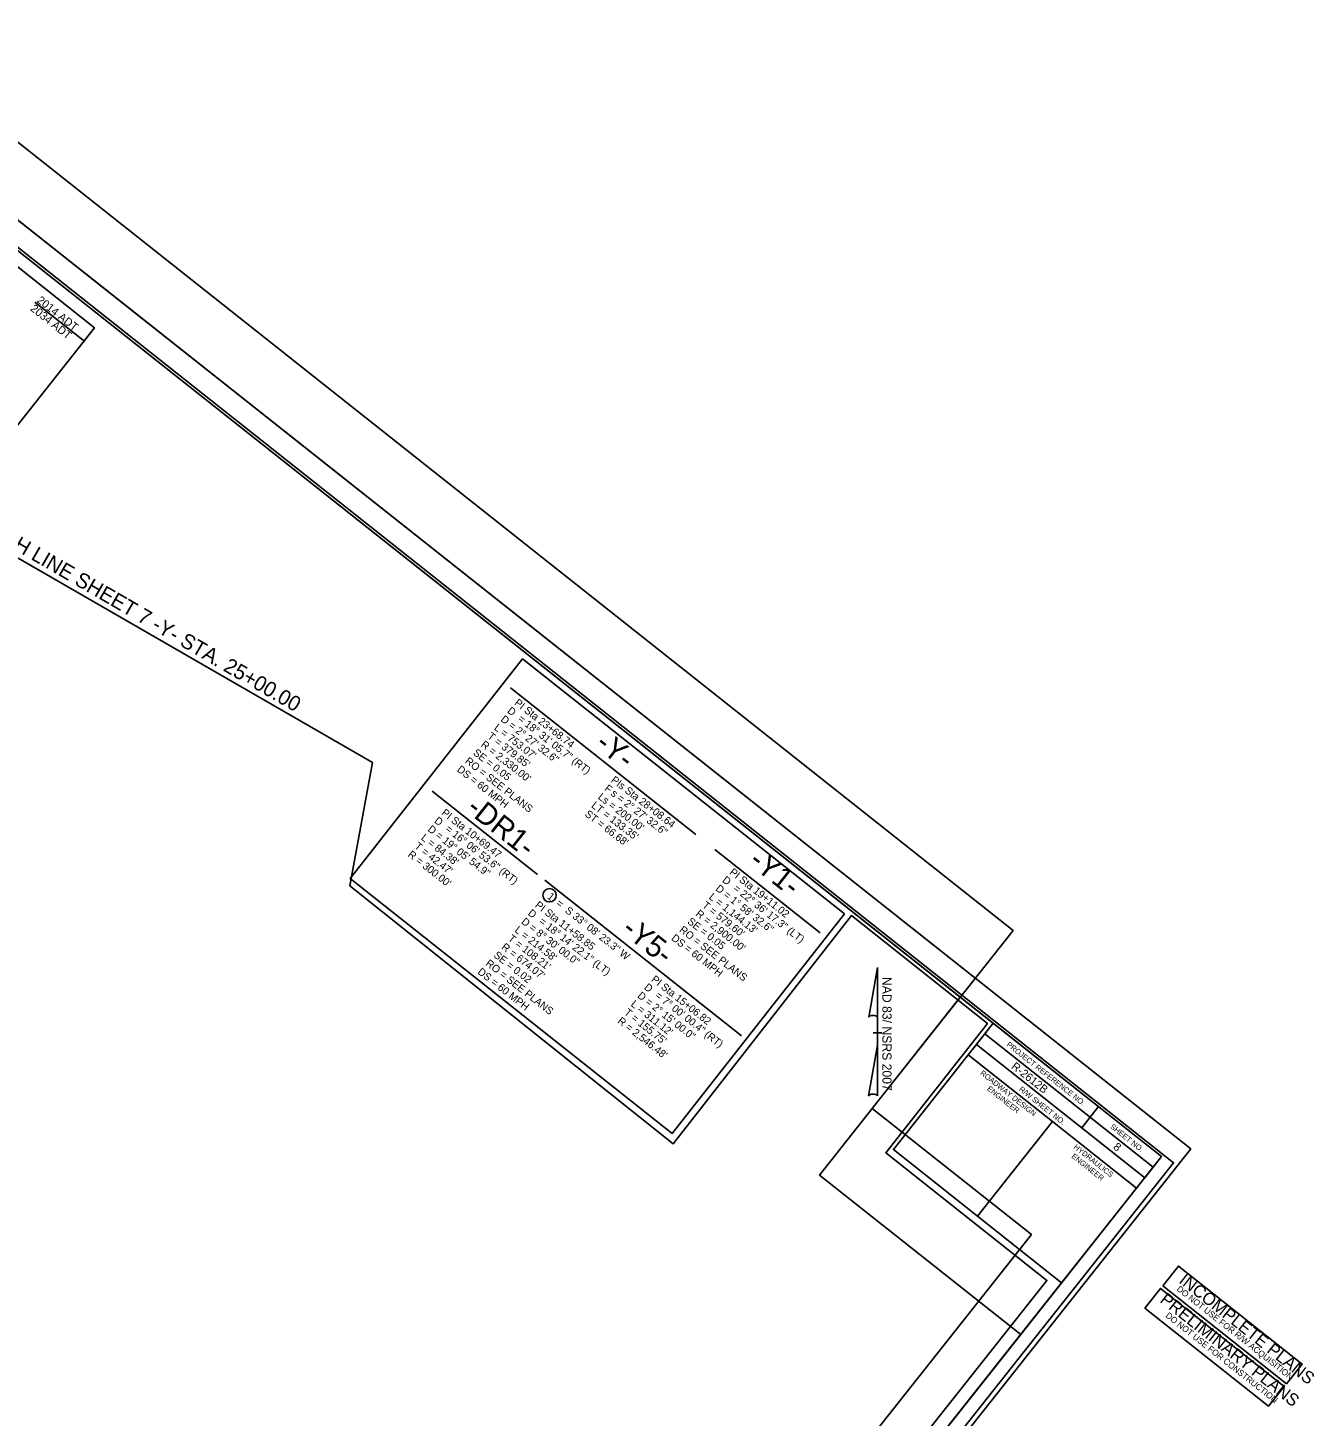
# Model space of a CAD drawing. Extents: x 1781865 to 1783979, y 813086 to 815120.
# Drawn here: x 1782780 to 1783979, y 813782 to 815076 of the extents above; entities that cross this region are included whole.
import ezdxf

# ---------------------------------------------------------------- set-up
doc = ezdxf.new("R2010")
doc.units = 0
for name, color, linetype in [('Matchline', 7, 'Continuous'), ('Matchline Text', 7, 'Continuous'), ('Old_Level_45', 7, 'Continuous'), ('Prop Horizontal Alignment Curve and Spiral Data', 7, 'Continuous'), ('Prop Horizontal Alignment Direction Label', 7, 'Continuous'), ('Prop Horizontal Alignment Station Label', 7, 'Continuous'), ('Prop North Arrow NAD83 for Plan Sheets CELL', 7, 'Continuous'), ('Sheet Clip Boundary CELL', 7, 'Continuous'), ('Sheet Cutting Line CELL', 7, 'Continuous'), ('Sheet Data Field CELL', 7, 'Continuous'), ('Sheet Layout Plan Border', 7, 'Continuous'), ('Sheet North Arrow Point CELL', 7, 'Continuous'), ('Sheet Plan CELL', 7, 'Continuous'), ('Sheet Plan Layout CELL', 7, 'Continuous'), ('Sheet Plot Border Inside CELL', 7, 'Continuous'), ('Sheet Plot Border Outside CELL', 7, 'Continuous'), ('Sheet Sticker Incomplete CELL', 7, 'Continuous'), ('Sheet Sticker Preliminary CELL', 7, 'Continuous')]:
    doc.layers.add(name, color=color, linetype=linetype)

msp = doc.modelspace()

# ---------------------------------------------------------------- linework, layer by layer
at = {"layer": 'Matchline'}
msp.add_line((1783101.5, 814390.8), (1782552.2, 814707.5), dxfattribs=at)
at = {"layer": 'Old_Level_45'}
msp.add_line((1782786.8, 814819.8), (1782833.2, 814783.1), dxfattribs=at)
msp.add_lwpolyline([(1782528.7, 814764.8), (1782664.8, 814936.7), (1782842.3, 814796.1), (1782706.3, 814624.2)], close=True, dxfattribs=at)
at = {"layer": 'Prop Horizontal Alignment Curve and Spiral Data'}
msp.add_circle((1783266.5, 814267.1), 6.26, dxfattribs=at)
at = {"layer": 'Prop Horizontal Alignment Station Label'}
for p, q in [((1783230.2, 814460.6), (1783402.9, 814323.8)), ((1783157.2, 814364.2), (1783255.3, 814286.6)), ((1783420.6, 814309.8), (1783518.7, 814232.2)), ((1783262.1, 814281.2), (1783445.5, 814136))]:
    msp.add_line(p, q, dxfattribs=at)
msp.add_lwpolyline([(1783241.3, 814487.4), (1783541.4, 814249.8), (1783380.8, 814045), (1783080.7, 814282.6)], close=True, dxfattribs=at)
at = {"layer": 'Prop North Arrow NAD83 for Plan Sheets CELL'}
for p, q in [((1783564, 814153.6), (1783572.2, 814199.9)), ((1783572.2, 814199.9), (1783572.2, 814199.9)), ((1783572.2, 814199.9), (1783572.2, 814199.9)), ((1783572.2, 814199.9), (1783572.2, 814152.1)), ((1783572.2, 814127.3), (1783572.2, 814153.5)), ((1783572.2, 814152.1), (1783572.2, 814153.5)), ((1783571.8, 814138.9), (1783568.2, 814138.9)), ((1783568.2, 814138.9), (1783568.2, 814138.9)), ((1783568.3, 814138.9), (1783576.3, 814138.9)), ((1783572.2, 814127.3), (1783563.9, 814080.1)), ((1783572.3, 814080.3), (1783572.2, 814127.3))]:
    msp.add_line(p, q, dxfattribs=at)
for centre, start_param, end_param in [((1783568.1, 814153.1), 0.216388, 2.908219), ((1783568.1, 814079.9), 0.201328, 3.141593)]:
    msp.add_ellipse(centre, major_axis=(4.23, -0.03), ratio=0.461098, start_param=start_param, end_param=end_param, dxfattribs=at)
at = {"layer": 'Sheet Clip Boundary CELL'}
msp.add_lwpolyline([(1782552.2, 814707.5), (1782111.4, 814173.2), (1782528.7, 813842.8), (1782497.5, 813772.1), (1782783.1, 813661.2), (1782870.1, 813592.2), (1782852, 813569.4), (1783166.6, 813320.4), (1783243.8, 813293.9), (1783730.1, 813908.2), (1783580.1, 814026.9), (1783674.7, 814147.7), (1783547.9, 814248.1), (1783381.9, 814035.5), (1783080.3, 814276), (1783101.5, 814390.8)], close=True, dxfattribs=at)
at = {"layer": 'Sheet Cutting Line CELL'}
msp.add_line((1783864.3, 814030.7), (1782544.4, 815075.6), dxfattribs=at)
at = {"layer": 'Sheet Layout Plan Border'}
msp.add_lwpolyline([(1782097.5, 814162.5), (1783195.2, 813293.5), (1783715.7, 813950.9), (1783567.3, 814068.4), (1783698.6, 814234.2), (1782749.3, 814985.7)], close=True, dxfattribs=at)
at = {"layer": 'Sheet North Arrow Point CELL'}
msp.add_line((1783630.7, 814194.9), (1783630.7, 814194.9), dxfattribs=at)
at = {"layer": 'Sheet Plan CELL'}
for p, q in [((1783672.3, 814137.9), (1783829.2, 814013.7)), ((1783664.6, 814128.1), (1783656.8, 814118.3)), ((1783664.6, 814128.1), (1783821.4, 814003.9)), ((1783664.6, 814128.1), (1783821.4, 814003.9)), ((1783778.1, 814070.1), (1783762.6, 814050.5)), ((1783735.3, 814056.2), (1783665.5, 813968))]:
    msp.add_line(p, q, dxfattribs=at)
for points in [[(1783837, 814023.6), (1782660.9, 814954.7), (1782009.2, 814131.4), (1783185.2, 813200.3)], [(1782009.2, 814131.4), (1782660.9, 814954.7), (1783680.1, 814147.8), (1783587, 814030.1), (1783743.8, 813905.9), (1783185.2, 813200.3)], [(1783680.1, 814147.8), (1783837, 814023.6), (1783821.4, 814003.9), (1783664.6, 814128.1)], [(1783656.8, 814118.3), (1783735.3, 814056.2), (1783665.4, 813968), (1783587, 814030.1)], [(1783735.3, 814056.2), (1783813.7, 813994.1), (1783743.8, 813905.9), (1783665.4, 813968)]]:
    msp.add_lwpolyline(points, close=True, dxfattribs=at)
at = {"layer": 'Sheet Plan Layout CELL'}
for points in [[(1782660.9, 814954.7), (1782009.2, 814131.4), (1783185.2, 813200.4), (1783705.7, 813857.8), (1783518.1, 814006.3), (1783649.4, 814172.1)], [(1783518.1, 814006.3), (1783705.7, 813857.8), (1783837, 814023.6), (1783649.4, 814172.1)]]:
    msp.add_lwpolyline(points, close=True, dxfattribs=at)
at = {"layer": 'Sheet Plot Border Inside CELL'}
msp.add_lwpolyline([(1781887.3, 814224.7), (1783193.5, 813190.6), (1783848.3, 814017.8), (1782542.1, 815051.9)], close=True, dxfattribs=at)
at = {"layer": 'Sheet Plot Border Outside CELL'}
msp.add_lwpolyline([(1781864.7, 814217.1), (1783184.6, 813172.1), (1783864.3, 814030.7), (1782544.4, 815075.6)], close=True, dxfattribs=at)
at = {"layer": 'Sheet Sticker Incomplete CELL'}
msp.add_lwpolyline([(1783838.1, 813903), (1783852.7, 813921.5), (1783968, 813830.2), (1783953.4, 813811.8)], close=True, dxfattribs=at)
at = {"layer": 'Sheet Sticker Preliminary CELL'}
msp.add_lwpolyline([(1783821.4, 813882.3), (1783836, 813900.7), (1783951.2, 813809.4), (1783936.7, 813791)], close=True, dxfattribs=at)

# ---------------------------------------------------------------- texts
at = {"layer": 'Matchline Text'}
msp.add_text('MATCH LINE SHEET 7 -Y- STA. 25+00.00', height=14, rotation=329.9225, dxfattribs=at).set_placement((1782720.2, 814616.7))
at = {"layer": 'Old_Level_45'}
for s, p in [(' 2014 ADT', (1782785.8, 814822.2)), (' 2034 ADT', (1782779.7, 814814.5))]:
    msp.add_text(s, height=7.5, rotation=321.6312, dxfattribs=at).set_placement(p)
at = {"layer": 'Prop Horizontal Alignment Curve and Spiral Data'}
for s, rotation, p in [('PI Sta 23+68.74', 321.9988, (1783233.2, 814445.3)), ('D = 2%%d 27\' 32.6"', 321.9988, (1783220.4, 814430)), ('D', 321.9988, (1783226.5, 814437.9)), ("L = 753.07'", 321.9988, (1783214.2, 814422.1)), ('= 18%%d 31\' 05.7" (RT)', 321.9988, (1783236.4, 814430.3)), ("R = 2,330.00'", 321.9988, (1783201.9, 814406.3)), ("T = 379.85'", 321.9988, (1783208.1, 814414.2)), ('RO = SEE PLANS', 321.9988, (1783187.1, 814391)), ('SE = 0.05', 321.9988, (1783194.6, 814398.8)), ('DS = 60 MPH', 321.9988, (1783179.6, 814383.2)), ('F', 322.4509, (1783317.1, 814365.4)), ('PIs Sta 28+08.64', 322.4509, (1783323.2, 814373.3)), ("Ls = 200.00'", 322.4509, (1783311, 814357.5)), ('s = 2%%d 27\' 32.6"', 322.4509, (1783323.1, 814360.8)), ('PI Sta 10+69.47', 321.9072, (1783165.2, 814342.8)), ("ST = 66.68'", 322.4509, (1783298.8, 814341.6)), ("LT = 133.35'", 322.4509, (1783304.9, 814349.6)), ('D = 19%%d 05\' 54.9"', 321.9072, (1783152.3, 814327.5)), ('D', 321.9072, (1783158.5, 814335.4)), ('= 16%%d 06\' 53.6" (RT)', 321.9072, (1783168.8, 814327.7)), ("L = 84.38'", 321.9072, (1783146.1, 814319.6)), ("R = 300.00'", 321.9072, (1783133.8, 814303.9)), ("T = 42.47'", 321.9072, (1783140, 814311.7)), ('PI Sta 19+11.02', 321.6272, (1783433.7, 814287.5)), ('D', 321.6272, (1783426.9, 814280.1)), ("L = 1,144.13'", 321.6272, (1783414.5, 814264.4)), ('D = 1%%d 58\' 32.6"', 321.6272, (1783420.7, 814272.2)), ('= 22%%d 36\' 17.3" (LT)', 321.6272, (1783437.2, 814272.3)), ('D', 322.1411, (1783245.7, 814249.3)), ('PI Sta 11+58.85', 322.1411, (1783252.4, 814256.8)), ("R = 2,900.00'", 321.6272, (1783402.1, 814248.7)), ("T = 579.60'", 321.6272, (1783408.3, 814256.6)), ('D = 8%%d 30\' 00.0"', 322.1411, (1783239.6, 814241.4)), ('= 18%%d 14\' 22.1" (LT)', 322.1411, (1783256, 814241.6)), ('SE = 0.05', 321.9988, (1783394.4, 814241.5)), ("T = 108.21'", 322.1411, (1783227.3, 814225.6)), ("L = 214.58'", 322.1411, (1783233.4, 814233.5)), ('DS = 60 MPH', 321.9988, (1783379.4, 814226)), ('RO = SEE PLANS', 321.9988, (1783386.9, 814233.7)), ('SE = 0.02', 321.9988, (1783213.8, 814210.1)), ("R = 674.07'", 322.1411, (1783221.1, 814217.7)), ('RO = SEE PLANS', 321.9988, (1783206.3, 814202.4)), ('DS = 60 MPH', 321.9988, (1783198.8, 814194.6)), ('PI Sta 15+06.82', 321.6309, (1783360.8, 814187.6)), ('D = 2%%d 15\' 00.0"', 321.6309, (1783347.9, 814172.4)), ('D', 321.6309, (1783354.1, 814180.2)), ('= 7%%d 00\' 00.4" (RT)', 321.6309, (1783364.4, 814172.5)), ("L = 311.12'", 321.6309, (1783341.7, 814164.5)), ("R = 2,546.48'", 321.6309, (1783329.3, 814148.8)), ("T = 155.75'", 321.6309, (1783335.5, 814156.7))]:
    msp.add_text(s, height=7, rotation=rotation, dxfattribs=at).set_placement(p)
at = {"layer": 'Prop Horizontal Alignment Direction Label'}
msp.add_text('1  =  S 33%%d 08\' 23.3" W', height=7, rotation=321.7069, dxfattribs=at).set_placement((1783263.8, 814264.8))
at = {"layer": 'Prop Horizontal Alignment Station Label'}
for s, p in [('-Y-', (1783308.1, 814405.9)), ('-DR1-', (1783187.9, 814345.8)), ('-Y1-', (1783451.2, 814296.6)), ('-Y5-', (1783332.6, 814232.8))]:
    msp.add_text(s, height=20, rotation=321.6309, dxfattribs=at).set_placement(p)
at = {"layer": 'Prop North Arrow NAD83 for Plan Sheets CELL'}
msp.add_text('NAD 83/ NSRS 2007', height=8.5, rotation=270, dxfattribs=at).set_placement((1783576.8, 814191))
at = {"layer": 'Sheet Data Field CELL'}
for s, p in [('R-2612B  ', (1783696.4, 814106.4)), ('8', (1783791.3, 814031.4))]:
    msp.add_text(s, height=7.5, rotation=321.6309, dxfattribs=at).set_placement(p)
at = {"layer": 'Sheet Plan CELL'}
for s, p in [('PROJECT REFERENCE NO.', (1783692.1, 814127.1)), ('ROADWAY DESIGN', (1783667.5, 814100.6)), ('ENGINEER', (1783673.8, 814086)), ('R/W SHEET NO.', (1783703.6, 814085.5)), ('SHEET NO.', (1783788.6, 814050.6)), ('HYDRAULICS', (1783754.6, 814031.6)), ('ENGINEER', (1783752.6, 814023))]:
    msp.add_text(s, height=5, rotation=321.6309, dxfattribs=at).set_placement(p)
at = {"layer": 'Sheet Sticker Incomplete CELL'}
for s, height, p in [('INCOMPLETE PLANS', 11.52, (1783852.4, 813906.6)), ('DO NOT USE FOR R/W ACQUISITION', 5.76, (1783850.6, 813899.2))]:
    msp.add_text(s, height=height, rotation=321.6309, dxfattribs=at).set_placement(p)
at = {"layer": 'Sheet Sticker Preliminary CELL'}
for s, height, p in [('PRELIMINARY PLANS', 11.52, (1783834.7, 813888.5)), ('DO NOT USE FOR CONSTRUCTION', 5.76, (1783840.2, 813874.4))]:
    msp.add_text(s, height=height, rotation=321.6309, dxfattribs=at).set_placement(p)

doc.saveas('drawing.dxf')
